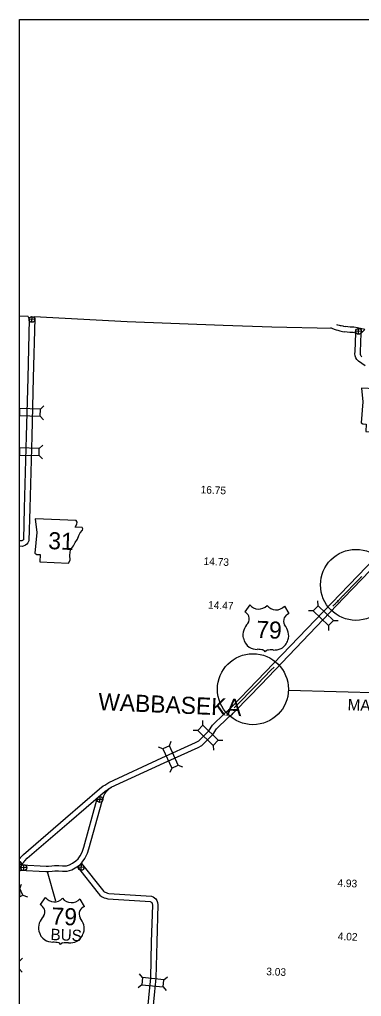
# Model space of a CAD drawing. Extents: x 1196286 to 1268366, y 2040822 to 2082115.
# Drawn here: x 1196286 to 1200093, y 2071244 to 2082115 of the extents above; entities that cross this region are included whole.
import ezdxf

# ---------------------------------------------------------------- set-up
doc = ezdxf.new("R2010")
doc.units = 0
for name, color, linetype in [('55', 7, 'Continuous'), ('Level 100', 7, 'Continuous'), ('Level 70', 7, 'Continuous'), ('Level 78', 7, 'Continuous'), ('Level 8', 7, 'Continuous'), ('Level 80', 7, 'Continuous'), ('Level 82', 7, 'Continuous'), ('Level 84', 7, 'Continuous'), ('Level 87', 7, 'Continuous'), ('Level 89', 7, 'Continuous'), ('Level 95', 7, 'Continuous'), ('Level 97', 7, 'Continuous'), ('Level 98', 7, 'Continuous')]:
    doc.layers.add(name, color=color, linetype=linetype)

msp = doc.modelspace()

# ---------------------------------------------------------------- linework, layer by layer
at = {"layer": '55'}
for points in [[(1196383, 2078809), (1196286, 2078814)], [(1199768, 2078677), (1199094, 2078692), (1198553, 2078711), (1197483, 2078750), (1196448, 2078805)]]:
    msp.add_lwpolyline(points, dxfattribs=at)
at = {"layer": 'Level 100'}
for p, q in [((1196457, 2078777), (1196392, 2078779)), ((1196423, 2078745), (1196425, 2078810)), ((1200059, 2078612), (1200062, 2078677)), ((1200093, 2078644), (1200028, 2078646)), ((1197180, 2073403), (1197182, 2073468)), ((1197214, 2073435), (1197149, 2073437)), ((1196286, 2072746), (1196286, 2072682)), ((1196312, 2072713), (1196286, 2072714)), ((1196332, 2072645), (1196334, 2072710)), ((1196972, 2072647), (1196974, 2072712)), ((1196286, 2072664), (1196286, 2072636)), ((1196289, 2072649), (1196286, 2072649)), ((1196365, 2072676), (1196301, 2072678)), ((1197006, 2072679), (1196941, 2072681))]:
    msp.add_line(p, q, dxfattribs=at)
for centre in [(1196424, 2078778), (1200060, 2078645), (1197181, 2073436), (1196333, 2072677), (1196973, 2072680)]:
    msp.add_circle(centre, 32.5, dxfattribs=at)
for centre, start, end in [((1196279, 2072714), 281.7447, 78.2553), ((1196256, 2072650), 334.6745, 25.3255)]:
    msp.add_arc(centre, 32.5, start, end, dxfattribs=at)
at = {"layer": 'Level 78'}
for points in [[(1200093, 2078012), (1200109, 2077859), (1200089, 2077628), (1200109, 2077615), (1200147, 2077613), (1200143, 2077532), (1200463, 2077518), (1200479, 2077551), (1200477, 2077604), (1200487, 2077665), (1200517, 2077712), (1200536, 2077746), (1200563, 2077783), (1200580, 2077823), (1200594, 2077856), (1200618, 2077883), (1200624, 2077900), (1200614, 2077913), (1200536, 2077917), (1200555, 2077951), (1200558, 2077974), (1200549, 2077992)], [(1196461, 2076560), (1196477, 2076407), (1196457, 2076177), (1196477, 2076163), (1196515, 2076162), (1196512, 2076081), (1196831, 2076067), (1196848, 2076099), (1196845, 2076153), (1196855, 2076213), (1196885, 2076260), (1196904, 2076295), (1196931, 2076332), (1196948, 2076372), (1196962, 2076404), (1196986, 2076431), (1196992, 2076449), (1196983, 2076462), (1196904, 2076465), (1196923, 2076500), (1196927, 2076523), (1196917, 2076541)]]:
    msp.add_lwpolyline(points, close=True, dxfattribs=at)
at = {"layer": 'Level 8'}
msp.add_line((1199280, 2074652), (1208377, 2074406), dxfattribs=at)
msp.add_lwpolyline([(1196286, 2082115), (1207541, 2082115), (1207563, 2069523), (1196286, 2069523)], close=True, dxfattribs=at)
for points in [[(1200095, 2075917), (1200089, 2075911), (1200084, 2075905), (1200078, 2075899), (1200072, 2075893), (1199995, 2075813)], [(1199995, 2075813), (1199944, 2075761), (1199938, 2075755), (1199933, 2075749), (1199927, 2075743), (1199921, 2075737), (1199915, 2075731), (1199909, 2075725), (1199904, 2075719), (1199898, 2075713), (1199892, 2075707), (1199886, 2075701), (1199880, 2075695), (1199875, 2075689), (1199869, 2075683), (1199863, 2075677), (1199857, 2075671), (1199851, 2075665), (1199846, 2075659), (1199840, 2075653), (1199834, 2075647), (1199828, 2075641), (1199822, 2075635), (1199816, 2075629), (1199811, 2075623), (1199805, 2075617), (1199799, 2075611), (1199793, 2075605), (1199787, 2075599), (1199782, 2075593), (1199775, 2075586)], [(1199085, 2074874), (1198935, 2074719), (1198677, 2074455)], [(1199120, 2074909), (1199085, 2074874)]]:
    msp.add_lwpolyline(points, dxfattribs=at)
for centre in [(1200032, 2075824), (1198885, 2074663)]:
    msp.add_circle(centre, 395, dxfattribs=at)
at = {"layer": 'Level 80'}
for p, q in [((1198849, 2075603), (1198794, 2075525)), ((1199235, 2075587), (1199283, 2075504)), ((1196592, 2072634), (1196686, 2072308)), ((1196573, 2072345), (1196517, 2072267)), ((1196958, 2072328), (1197007, 2072246))]:
    msp.add_line(p, q, dxfattribs=at)
for centre, radius, start, end in [((1198721, 2075411), 135, 28.3289, 57.5362), ((1198949, 2075680), 126, 217.623, 317.2181), ((1199142, 2075672), 126, 217.8778, 317.4729), ((1198752, 2075446), 92.5, 326.3584, 18.7587), ((1199318, 2075422), 92.5, 156.3372, 208.7375), ((1199346, 2075385), 135, 117.5597, 146.767), ((1198916, 2075267), 143, 158.5056, 194.9298), ((1198986, 2075246), 216, 136.5044, 160.2393), ((1199068, 2075243), 216, 14.8566, 38.5915), ((1198939, 2075266), 165, 192.6554, 234.6791), ((1199117, 2075259), 165, 300.4168, 342.4405), ((1199140, 2075257), 143, 340.1661, 16.5903), ((1198944, 2075318), 212, 241.625, 267.1258), ((1198923, 2074719), 388, 78.7421, 88.5018), ((1198987, 2075064), 37.2, 25.5822, 70.5343), ((1199052, 2075061), 37.2, 104.5616, 149.5137), ((1199086, 2074712), 388, 86.5941, 96.3538), ((1199116, 2075311), 212, 267.9701, 293.4709), ((1196444, 2072153), 135, 28.3289, 57.5362), ((1196673, 2072422), 126, 217.623, 317.2181), ((1196865, 2072414), 126, 217.8778, 317.4729), ((1196476, 2072188), 92.5, 326.3584, 18.7587), ((1197041, 2072163), 92.5, 156.3372, 208.7375), ((1197070, 2072126), 135, 117.5597, 146.767), ((1196639, 2072008), 143, 158.5056, 194.9298), ((1196709, 2071988), 216, 136.5044, 160.2393), ((1196792, 2071984), 216, 14.8566, 38.5915), ((1196864, 2071999), 143, 340.1661, 16.5903), ((1196662, 2072008), 165, 192.6554, 234.6791), ((1196840, 2072000), 165, 300.4168, 342.4405), ((1196667, 2072060), 212, 241.625, 267.1258), ((1196646, 2071460), 388, 78.7421, 88.5018), ((1196710, 2071806), 37.2, 25.5822, 70.5343), ((1196775, 2071803), 37.2, 104.5616, 149.5137), ((1196809, 2071453), 388, 86.5941, 96.3538), ((1196840, 2072052), 212, 267.9701, 293.4709)]:
    msp.add_arc(centre, radius, start, end, dxfattribs=at)
at = {"layer": 'Level 84'}
for points in [[(1201060, 2076456), (1200793, 2076458), (1200752, 2076456), (1200710, 2076450), (1200658, 2076436), (1200608, 2076420), (1200557, 2076398), (1200524, 2076380), (1200471, 2076347), (1200444, 2076326), (1200398, 2076283), (1200345, 2076229), (1199855, 2075719)], [(1201060, 2076396), (1200794, 2076398), (1200758, 2076396), (1200722, 2076392), (1200675, 2076378), (1200629, 2076364), (1200584, 2076345), (1200554, 2076328), (1200505, 2076298), (1200483, 2076280), (1200440, 2076240), (1200388, 2076187), (1199898, 2075678)], [(1199855, 2075719), (1198932, 2074759)], [(1199898, 2075678), (1198975, 2074717)], [(1197280, 2073625), (1197871, 2073898), (1198247, 2074069), (1198281, 2074087), (1198298, 2074103), (1198317, 2074122), (1198392, 2074200), (1198402, 2074211), (1198410, 2074222), (1198419, 2074240), (1198434, 2074262), (1198563, 2074388), (1198584, 2074407), (1198603, 2074421), (1198612, 2074426), (1198622, 2074437), (1198646, 2074463), (1198932, 2074759)], [(1197307, 2073571), (1197896, 2073843), (1198274, 2074015), (1198317, 2074038), (1198340, 2074061), (1198360, 2074080), (1198437, 2074159), (1198449, 2074174), (1198461, 2074191), (1198470, 2074209), (1198480, 2074223), (1198604, 2074344), (1198622, 2074360), (1198636, 2074371), (1198651, 2074379), (1198666, 2074397), (1198690, 2074422), (1198975, 2074717)], [(1196286, 2072650), (1196580, 2072634), (1196612, 2072635), (1196651, 2072638), (1196678, 2072642), (1196719, 2072640), (1196765, 2072638), (1196818, 2072639), (1196867, 2072653), (1196907, 2072674), (1196952, 2072705), (1196984, 2072737), (1197013, 2072779), (1197029, 2072809), (1197044, 2072840), (1197058, 2072888), (1197205, 2073417), (1197216, 2073452), (1197225, 2073478), (1197234, 2073497), (1197252, 2073521), (1197269, 2073541), (1197289, 2073558), (1197312, 2073573)], [(1196329, 2072825), (1196799, 2073227), (1197178, 2073555), (1197217, 2073586), (1197234, 2073596), (1197246, 2073604), (1197280, 2073625)], [(1196371, 2072782), (1196838, 2073182), (1197216, 2073509), (1197251, 2073537), (1197265, 2073545), (1197277, 2073553), (1197310, 2073572)], [(1196313, 2072709), (1196581, 2072694), (1196610, 2072695), (1196644, 2072697), (1196674, 2072702), (1196722, 2072700), (1196765, 2072698), (1196809, 2072699), (1196844, 2072708), (1196875, 2072726), (1196914, 2072752), (1196938, 2072775), (1196962, 2072810), (1196976, 2072836), (1196988, 2072861), (1197000, 2072905), (1197148, 2073433), (1197154, 2073454)], [(1196286, 2072776), (1196286, 2072777), (1196287, 2072778), (1196288, 2072779), (1196289, 2072780), (1196290, 2072781), (1196291, 2072783), (1196292, 2072784), (1196293, 2072785), (1196294, 2072786), (1196295, 2072787), (1196296, 2072788), (1196297, 2072789), (1196298, 2072791), (1196299, 2072792), (1196300, 2072793), (1196301, 2072794), (1196329, 2072825)], [(1196286, 2072650), (1196301, 2072685), (1196302, 2072686), (1196302, 2072687), (1196303, 2072688), (1196303, 2072689), (1196304, 2072690), (1196304, 2072691), (1196305, 2072692), (1196305, 2072693), (1196306, 2072695), (1196306, 2072696), (1196307, 2072697), (1196307, 2072698), (1196308, 2072699), (1196308, 2072700), (1196309, 2072701), (1196310, 2072702), (1196310, 2072703), (1196311, 2072704), (1196311, 2072705), (1196312, 2072706), (1196312, 2072707), (1196313, 2072709), (1196314, 2072710), (1196314, 2072711), (1196315, 2072712), (1196315, 2072713), (1196316, 2072714), (1196317, 2072715), (1196317, 2072716), (1196318, 2072717), (1196319, 2072718), (1196319, 2072719), (1196320, 2072720), (1196321, 2072721), (1196321, 2072722), (1196322, 2072723), (1196323, 2072724), (1196323, 2072725), (1196324, 2072726), (1196325, 2072727), (1196325, 2072728), (1196326, 2072729), (1196327, 2072730), (1196327, 2072731), (1196328, 2072732), (1196329, 2072733), (1196329, 2072734), (1196330, 2072735), (1196331, 2072736), (1196332, 2072737), (1196332, 2072738), (1196333, 2072739), (1196334, 2072740), (1196335, 2072741), (1196335, 2072742), (1196336, 2072743), (1196337, 2072744), (1196338, 2072745), (1196338, 2072746), (1196339, 2072747), (1196340, 2072747), (1196341, 2072748), (1196342, 2072749), (1196342, 2072750), (1196343, 2072751), (1196344, 2072752), (1196345, 2072753), (1196346, 2072754), (1196371, 2072782)], [(1196286, 2072681), (1196299, 2072680)], [(1196286, 2072649), (1196286, 2072650)]]:
    msp.add_lwpolyline(points, dxfattribs=at)
at = {"layer": 'Level 87'}
for points in [[(1196974, 2072725), (1197210, 2072430), (1197223, 2072412), (1197228, 2072409), (1197238, 2072405), (1197250, 2072399), (1197265, 2072394), (1197280, 2072390), (1197754, 2072359), (1197773, 2072353), (1197789, 2072342), (1197802, 2072330), (1197815, 2072312), (1197822, 2072289), (1197826, 2072263), (1197813, 2071849), (1197805, 2071446), (1197790, 2071300), (1197766, 2071069)], [(1196927, 2072689), (1197163, 2072393), (1197180, 2072370), (1197198, 2072356), (1197213, 2072350), (1197228, 2072343), (1197248, 2072336), (1197270, 2072331), (1197743, 2072300), (1197746, 2072298), (1197751, 2072295), (1197757, 2072290), (1197761, 2072284), (1197764, 2072277), (1197766, 2072260), (1197753, 2071851), (1197745, 2071449), (1197730, 2071306), (1197706, 2071072)]]:
    msp.add_lwpolyline(points, dxfattribs=at)
at = {"layer": 'Level 89'}
for points in [[(1199831, 2075648), (1199831, 2075649), (1199832, 2075650), (1199832, 2075651), (1199833, 2075651)], [(1199832, 2075635), (1199832, 2075636), (1199833, 2075636), (1199834, 2075637), (1199835, 2075638), (1199835, 2075638)]]:
    msp.add_lwpolyline(points, dxfattribs=at)
at = {"layer": 'Level 95'}
for points in [[(1196383, 2078809), (1196394, 2078778), (1196379, 2078129), (1196361, 2077480), (1196339, 2076679), (1196331, 2076330), (1196329, 2076325), (1196324, 2076320), (1196320, 2076317), (1196310, 2076313), (1196286, 2076314)], [(1196448, 2078805), (1196455, 2078788), (1196439, 2078127), (1196421, 2077478), (1196399, 2076678), (1196391, 2076315), (1196379, 2076292), (1196366, 2076276), (1196351, 2076264), (1196320, 2076252), (1196286, 2076254)], [(1199750, 2078688), (1199762, 2078682), (1199790, 2078669), (1199812, 2078662), (1199831, 2078657), (1199843, 2078655), (1199853, 2078652), (1199869, 2078648), (1199882, 2078644), (1199906, 2078640)], [(1199817, 2078722), (1199828, 2078719), (1199844, 2078715), (1199857, 2078712), (1199868, 2078709), (1199885, 2078705), (1199895, 2078702), (1199917, 2078698)], [(1200098, 2078360), (1200090, 2078369), (1200085, 2078378), (1200081, 2078386), (1200081, 2078393), (1200083, 2078416), (1200090, 2078625), (1200129, 2078665), (1200050, 2078683), (1200009, 2078691), (1199967, 2078693), (1199917, 2078698)], [(1200135, 2078263), (1200059, 2078314), (1200042, 2078333), (1200030, 2078351), (1200022, 2078372), (1200020, 2078394), (1200024, 2078421), (1200030, 2078626), (1200002, 2078632), (1199962, 2078634), (1199906, 2078640)]]:
    msp.add_lwpolyline(points, dxfattribs=at)
at = {"layer": 'Level 98'}
for p, q in [((1196518, 2077779), (1196557, 2077816)), ((1196286, 2077786), (1196286, 2077707)), ((1196516, 2077700), (1196552, 2077662)), ((1196506, 2077342), (1196545, 2077379)), ((1196286, 2077349), (1196286, 2077269)), ((1196504, 2077263), (1196540, 2077225)), ((1199610, 2075592), (1199609, 2075645)), ((1199555, 2075535), (1199502, 2075534)), ((1199781, 2075428), (1199834, 2075429)), ((1199727, 2075371), (1199728, 2075318)), ((1198328, 2074261), (1198327, 2074313)), ((1198272, 2074204), (1198220, 2074203)), ((1197882, 2074001), (1197832, 2074019)), ((1197954, 2074033), (1197973, 2074083)), ((1198443, 2074038), (1198444, 2073985)), ((1198498, 2074095), (1198551, 2074096)), ((1197980, 2073784), (1197961, 2073735)), ((1198052, 2073817), (1198102, 2073798)), ((1196290, 2072444), (1196308, 2072493)), ((1196286, 2072442), (1196286, 2072354)), ((1196324, 2072372), (1196374, 2072354)), ((1196286, 2071637), (1196319, 2071669)), ((1196286, 2071546), (1196315, 2071515)), ((1197656, 2071454), (1197622, 2071494)), ((1197892, 2071430), (1197933, 2071463)), ((1197648, 2071375), (1197607, 2071341)), ((1197884, 2071351), (1197918, 2071310))]:
    msp.add_line(p, q, dxfattribs=at)
for points in [[(1196286, 2077707), (1196516, 2077700), (1196518, 2077779), (1196286, 2077786)], [(1196286, 2077269), (1196504, 2077263), (1196506, 2077342), (1196286, 2077349)], [(1196286, 2072354), (1196324, 2072372), (1196290, 2072444), (1196286, 2072442)]]:
    msp.add_lwpolyline(points, dxfattribs=at)
for points in [[(1199555, 2075535), (1199727, 2075371), (1199781, 2075428), (1199610, 2075592)], [(1198272, 2074204), (1198443, 2074038), (1198498, 2074095), (1198328, 2074261)], [(1198052, 2073817), (1197954, 2074033), (1197882, 2074001), (1197980, 2073784)], [(1197648, 2071375), (1197884, 2071351), (1197892, 2071430), (1197656, 2071454)]]:
    msp.add_lwpolyline(points, close=True, dxfattribs=at)

# ---------------------------------------------------------------- texts
at = {"layer": 'Level 70'}
for s, height, p in [('WABBASEKA', 190.1, (1197160, 2074431)), ('MANAGEMENT', 126.7, (1199937, 2074429))]:
    msp.add_text(s, height=height, rotation=357.548, dxfattribs=at).set_placement(p)
at = {"layer": 'Level 78'}
msp.add_text('31', height=190.1, rotation=357.548, dxfattribs=at).set_placement((1196603, 2076223))
at = {"layer": 'Level 80'}
for s, height, p in [('79', 190.1, (1198919, 2075235)), ('79', 190.1, (1196639, 2072045)), ('BUS', 126.7, (1196629, 2071872))]:
    msp.add_text(s, height=height, rotation=357.548, dxfattribs=at).set_placement(p)
at = {"layer": 'Level 82'}
for s, p in [('14.73', (1198334, 2076046)), ('14.47', (1198384, 2075560)), ('4.93', (1199824, 2072466)), ('4.02', (1199828, 2071873))]:
    msp.add_text(s, height=84.5, rotation=357.548, dxfattribs=at).set_placement(p)
at = {"layer": 'Level 97'}
for s, p in [('16.75', (1198301, 2076843)), ('3.03', (1199032, 2071481))]:
    msp.add_text(s, height=84.5, rotation=357.548, dxfattribs=at).set_placement(p)

doc.saveas('drawing.dxf')
